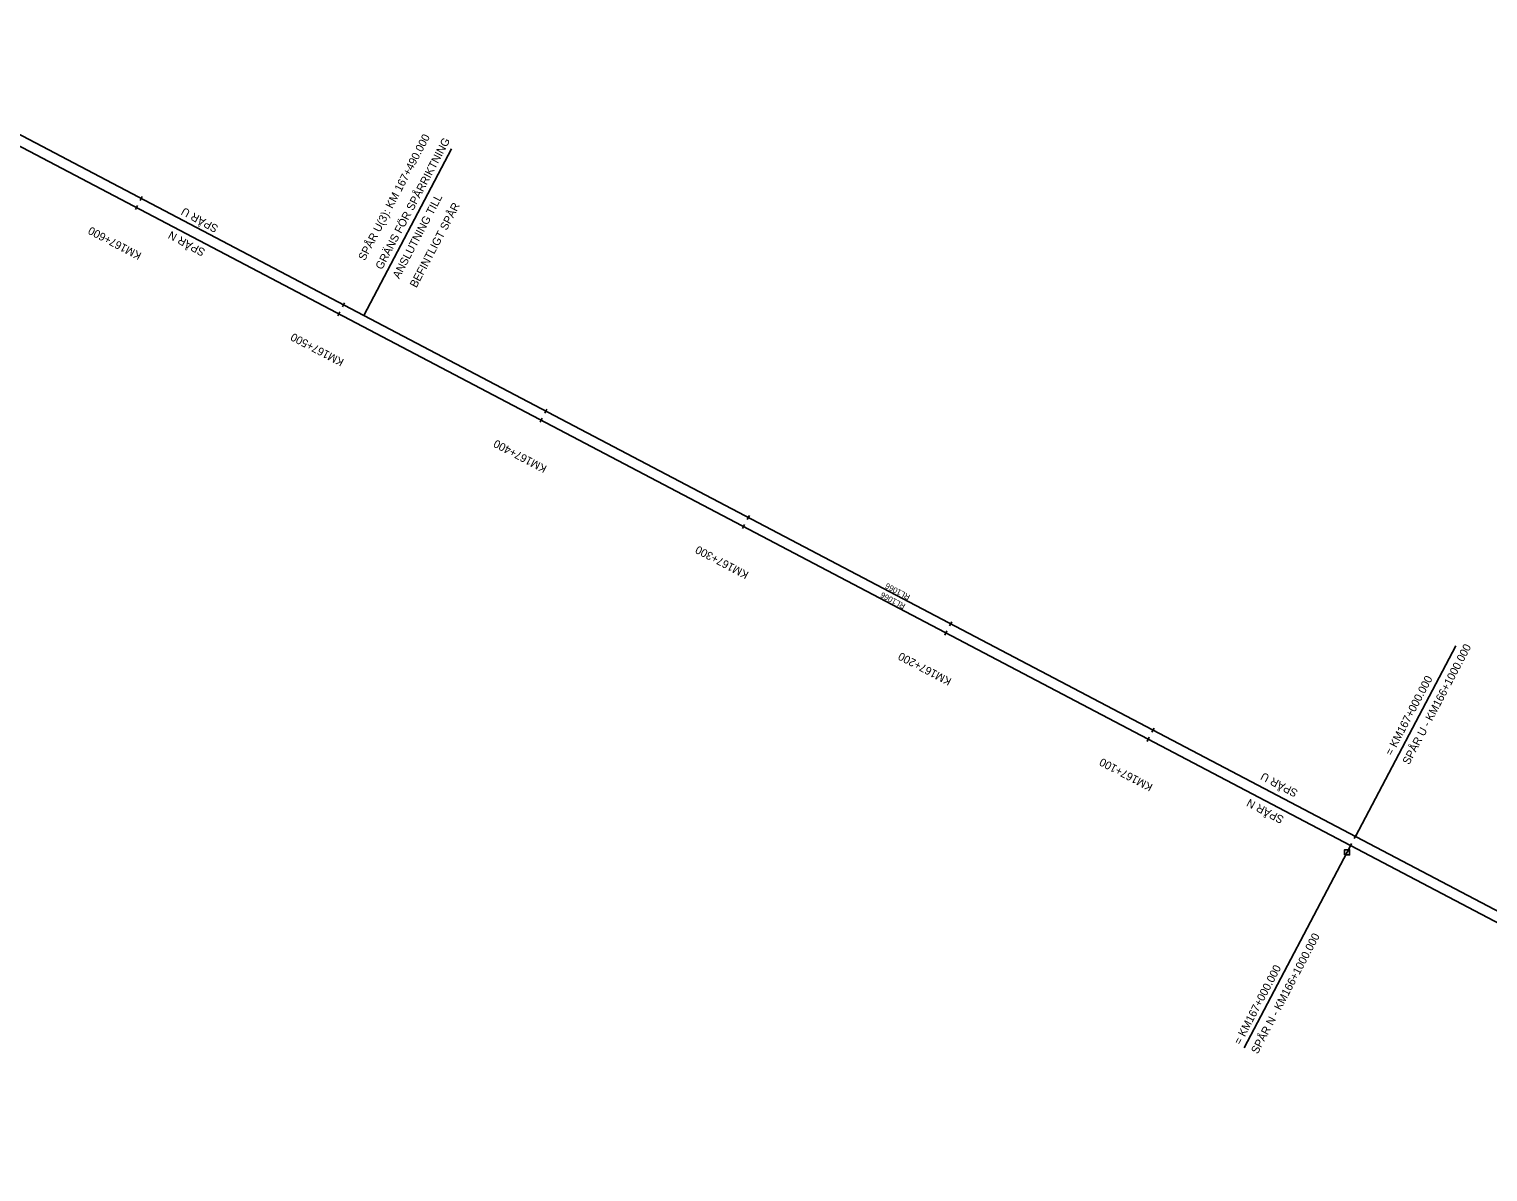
# Model space of a CAD drawing. Extents: x 185262 to 188870, y 6548921 to 6550022.
# Drawn here: x 187573 to 188211, y 6549174 to 6549674 of the extents above; entities that cross this region are included whole.
import ezdxf

# ---------------------------------------------------------------- set-up
doc = ezdxf.new("R2010")
doc.units = 0
for name, color, linetype in [('Befintligt spår som justeras', 7, 'Continuous'), ('Gräns för anslutning L', 7, 'Continuous'), ('Gräns för anslutning T', 7, 'Continuous'), ('Kilometertavla P', 7, 'Continuous'), ('Konnektion längdmätning L', 7, 'Continuous'), ('Konnektion längdmätning T', 7, 'Continuous'), ('Längdm markering (primär) L', 7, 'Continuous'), ('Längdmätning T', 7, 'Continuous'), ('Spår bef projekterat behålls L', 7, 'Continuous'), ('Spår nr T', 7, 'Continuous'), ('Spårgeometri T', 7, 'Continuous')]:
    doc.layers.add(name, color=color, linetype=linetype)

msp = doc.modelspace()

# ---------------------------------------------------------------- linework, layer by layer
at = {"layer": 'Befintligt spår som justeras'}
for p, q in [((187719.61, 6549548.75), (187481.29, 6549674.04)), ((187573.24, 6549620.62), (187479.19, 6549670.06))]:
    msp.add_line(p, q, dxfattribs=at)
at = {"layer": 'Gräns för anslutning L'}
msp.add_line((187719.61, 6549548.75), (187757.97, 6549621.71), dxfattribs=at)
at = {"layer": 'Kilometertavla P'}
msp.add_lwpolyline([(188148.57, 6549312.69), (188150.82, 6549312.69), (188150.82, 6549314.94), (188148.57, 6549314.94)], close=True, dxfattribs=at)
at = {"layer": 'Konnektion längdmätning L'}
for points in [[(188153.33, 6549320.73), (188197.22, 6549404.22)], [(188151.24, 6549316.75), (188104.7, 6549228.24)]]:
    msp.add_lwpolyline(points, dxfattribs=at)
at = {"layer": 'Längdm markering (primär) L'}
for points in [[(187619.69, 6549595.07), (187620.62, 6549596.84)], [(187621.78, 6549599.05), (187622.72, 6549600.82)], [(187710.3, 6549552.52), (187711.23, 6549554.29)], [(187708.2, 6549548.53), (187709.13, 6549550.3)], [(187798.81, 6549505.98), (187799.74, 6549507.75)], [(187796.72, 6549502), (187797.65, 6549503.77)], [(187885.23, 6549455.47), (187886.16, 6549457.24)], [(187887.32, 6549459.45), (187888.26, 6549461.22)], [(187975.84, 6549412.92), (187976.77, 6549414.69)], [(187973.74, 6549408.93), (187974.67, 6549410.7)], [(188064.35, 6549366.38), (188065.28, 6549368.15)], [(188062.26, 6549362.4), (188063.19, 6549364.17)], [(188150.77, 6549315.87), (188151.7, 6549317.64)], [(188152.87, 6549319.85), (188153.8, 6549321.62)]]:
    msp.add_lwpolyline(points, dxfattribs=at)
at = {"layer": 'Spår bef projekterat behålls L'}
for p, q in [((188422.73, 6549174.02), (187573.24, 6549620.62)), ((188424.82, 6549178.01), (187719.61, 6549548.75))]:
    msp.add_line(p, q, dxfattribs=at)

# ---------------------------------------------------------------- texts
at = {"layer": 'Gräns för anslutning T'}
for s, p in [('SPÅR U(3): KM 167+490.000', (187720.05, 6549572.47)), ('GRÄNS FÖR SPÅRRIKTNING', (187727.57, 6549568.52)), ('ANSLUTNING TILL ', (187735.09, 6549564.56)), ('BEFINTLIGT SPÅR', (187742.62, 6549560.61))]:
    msp.add_text(s, height=3.5, rotation=62.26802, dxfattribs=at).set_placement(p)
at = {"layer": 'Konnektion längdmätning T'}
for s, p in [('SPÅR U - KM166+1000.000', (188176.81, 6549351.9)), ('= KM167+000.000 ', (188169.29, 6549355.85)), ('SPÅR N - KM166+1000.000 ', (188110.58, 6549225.36)), ('= KM167+000.000', (188103.06, 6549229.31))]:
    msp.add_text(s, height=3.5, rotation=62.26802, dxfattribs=at).set_placement(p)
at = {"layer": 'Längdmätning T'}
for s, p in [('KM167+600', (187622.7, 6549575.98)), ('KM167+500', (187711.25, 6549529.42)), ('KM167+400', (187799.99, 6549482.77)), ('KM167+300', (187888.29, 6549436.35)), ('KM167+200', (187977, 6549389.71)), ('KM167+100', (188065.03, 6549343.43))]:
    msp.add_text(s, height=3.5, rotation=152.26802, dxfattribs=at).set_placement(p)
at = {"layer": 'Spår nr T'}
for s, rotation, p in [('SPÅR U', 151.32776, (187656.3, 6549587.84)), ('SPÅR N', 151.32776, (187650.61, 6549577.48)), ('SPÅR U', 152.26802, (188128.5, 6549340.87)), ('SPÅR N', 152.26802, (188122.4, 6549329.27))]:
    msp.add_text(s, height=3.5, rotation=rotation, dxfattribs=at).set_placement(p)
at = {"layer": 'Spårgeometri T'}
for p in [(187958.88, 6549426.35), (187956.78, 6549422.37)]:
    msp.add_text('RL1066', height=2.5, rotation=152.26802, dxfattribs=at).set_placement(p)

doc.saveas('drawing.dxf')
